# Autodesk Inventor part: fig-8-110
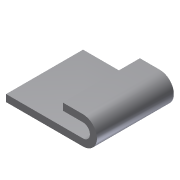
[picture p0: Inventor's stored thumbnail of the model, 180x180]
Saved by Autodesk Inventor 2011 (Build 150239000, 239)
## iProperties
Created: 2009-09
Part Number: fig-8-110
Document SubType Name: Modeling
Designer: Sham
Density: 1 g/cm^3
Author: Sham
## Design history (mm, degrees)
sketch "Sketch1"
  geometry: L1 (-33.976, 22)-(0, 22); L2 (0, 22)-(0, 0); L3 (0, 0)-(-33.976, 0); L4 (-33.976, 0)-(-33.976, 22)
  constraints: 8 end point, 2 parallel, 1 horizontal, 1 perpendicular
extrude "Extrusion1" new body sketch "Sketch1" distance "d0" = 2; taper "d1" = 0 deg
sketch "Sketch2"
  geometry: L1 (-12, 22)-(-12, 0)
  constraints: 2 end point
feature "Bend Part1" sketch "Sketch2" dims "d2" = 2, "d3" = 180 deg
body "Solid1"
